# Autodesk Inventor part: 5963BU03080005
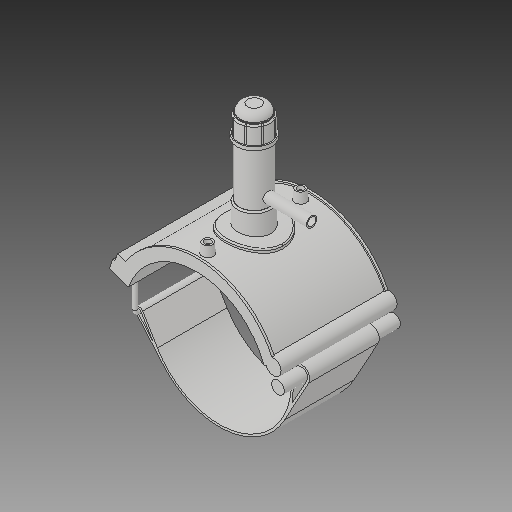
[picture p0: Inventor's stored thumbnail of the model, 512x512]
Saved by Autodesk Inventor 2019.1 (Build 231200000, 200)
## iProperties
Created: 2017-07
Part Number: 5963BU03080005
Material: Generic
Description: PLASSON TAPPING SADDLE 8''IPS x 1 1/2''CTS
Document SubType Name: Modeling
Designer: KIM
Mass: 1712.7 g
Surface Area: 2671.49 cm^2
Volume: 1712.7 cm^3
Density: 1 g/cm^3
Appearance: Default
Author: KIM
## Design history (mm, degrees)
derived "5963B.ipt"
feature "Solid1::5963B.ipt"
feature "Solid2::5963B.ipt"
feature "Solid4::5963B.ipt"
feature "Solid5::5963B.ipt"
tag "TaggingFeature1" dims "d0" = 218.7
body "Solid1"
body "Solid2"
other parameters: "d2" = 269.748, "d3" = 54.675, "d4" = 176.022, "d5" = 0, "d6" = 0.1, "d8" = 0, "d19" = 6, "d20" = 6, "d21" = 105.6132, "d23" = 0, "d24" = 52.8066, "d26" = 0, "d29" = 3, "d30" = 72.9, "d31" = 6, "d32" = 0, "d33" = 0, "d34" = 0.6, "d40" = 129.64536, "d41" = 87.48, "d43" = 0, "d45" = 0, "d47" = 230.2722, "d70" = 15, "d72" = 0, "d73" = 6, "d75" = 5, "d76" = 0, "d77" = 10.935, "d78" = 139.35, "d79" = 15, "d80" = 70.4088, "d82" = 5 deg, "d84" = 4, "d85" = 14, "d86" = 0, "d87" = 3, "d88" = 0, "d89" = 1, "d90" = 1, "d91" = 140.8176, "d92" = 0, "d93" = 0.5, "d94" = 115.10526, "d96" = 254.30436, "d97" = 3.52044, "d98" = 0, "d102" = 2.187, "d120" = 140 deg, "d121" = 24.228, "d122" = 20 deg, "d123" = 498.636, "d124" = 149.5908, "d126" = 0, "d143" = 225.261, "d145" = 23.55231, "d149" = 3.2805, "d150" = 25.90754, "d153" = 176.022, "d154" = 0, "d156" = 124.659, "d157" = 160 deg, "d159" = 6.1236, "d161" = 3.2805, "d162" = 105.6132, "d163" = 0, "d164" = 109.35, "d167" = 21.87, "d168" = 121.61854, "d170" = 3.2805, "d172" = 0, "d173" = 1, "d175" = 109.35, "d176" = 20 deg, "d177" = 15.309, "d178" = 30.618, "d180" = 0, "d183" = 12.2472, "d184" = 12.2472, "d185" = 57.20715, "d186" = 57.20715, "d187" = 124.659, "d188" = 9.1854, "d189" = 15.309, "d190" = 0, "d191" = 186.9885, "d193" = 6.1236, "d194" = 6.16077, "d195" = 90 deg, "d197" = 0, "d199" = 0, "d200" = 15.309, "d202" = 0, "d203" = 177.038, "d204" = 49.8636, "d205" = 36.7416, "d206" = 44.6148, "d207" = 132.7785, "d208" = 138.08964, "d209" = 164.64534, "d210" = 45.13968, "d211" = 52.488, "d212" = 41.9904, "d213" = 51.4116, "d216" = 0, "d217" = 21.87, "d218" = 10.935, "d219" = 2.187, "d222" = 218.7, "d224" = 0, "d230" = 2.187, "d233" = 6, "d236" = 89.916, "d237" = 52.8066, "d238" = 6.02433, "d240" = 52.8066, "d241" = 52.8066, "d242" = 52.8066, "d243" = 6, "d244" = 52.8066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
